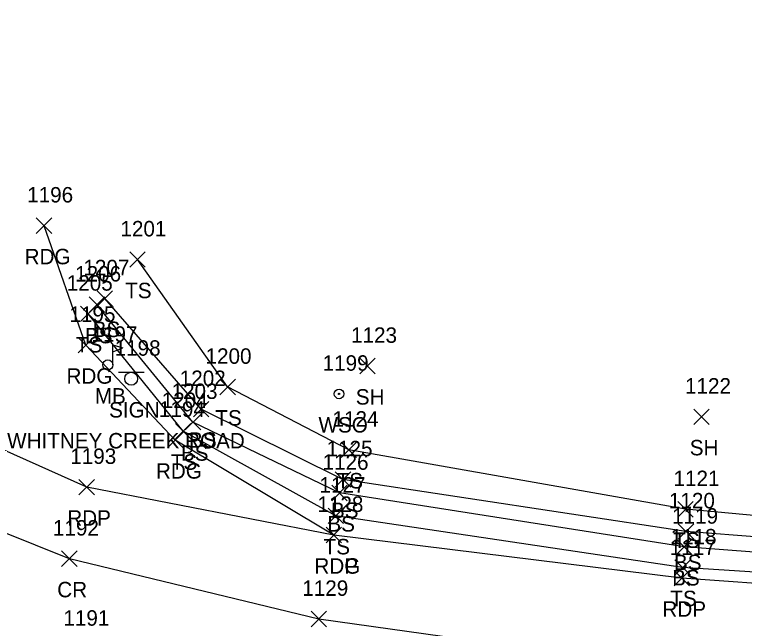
# Model space of a CAD drawing. Extents: x 1401404 to 1403982, y 557481 to 559873.
# Drawn here: x 1403353.7 to 1403448.2, y 558593.7 to 558673.1 of the extents above; entities that cross this region are included whole.
import ezdxf

# ---------------------------------------------------------------- set-up
doc = ezdxf.new("R2010")
doc.units = 0
for name, color, linetype in [('L_A', 7, 'Continuous'), ('L_I', 7, 'Continuous'), ('L_TIC', 7, 'Continuous'), ('LELB', 7, 'Continuous'), ('LMB', 7, 'Continuous'), ('P_A', 7, 'Continuous'), ('P_I', 7, 'Continuous'), ('P_TIC', 7, 'Continuous'), ('PET', 7, 'Continuous'), ('PEU', 7, 'Continuous'), ('PRC', 7, 'Continuous'), ('S_A', 7, 'Continuous'), ('S_C', 7, 'Continuous'), ('S_I', 7, 'Continuous'), ('SSGN', 7, 'Continuous'), ('U_A', 7, 'Continuous'), ('U_I', 7, 'Continuous'), ('UWV', 7, 'Continuous')]:
    doc.layers.add(name, color=color, linetype=linetype)

msp = doc.modelspace()

# ---------------------------------------------------------------- linework, layer by layer
at = {"layer": 'L_TIC'}
for points in [[(1403368.639, 558640.429), (1403370.639, 558642.429)], [(1403370.639, 558640.429), (1403368.639, 558642.429)], [(1403364.413, 558635.397), (1403366.413, 558637.397)], [(1403366.413, 558635.397), (1403364.413, 558637.397)], [(1403363.402, 558634.589), (1403365.402, 558636.589)], [(1403365.402, 558634.589), (1403363.402, 558636.589)], [(1403362.259, 558633.405), (1403364.259, 558635.405)], [(1403364.259, 558633.405), (1403362.259, 558635.405)], [(1403398.403, 558626.651), (1403400.403, 558628.651)], [(1403400.403, 558626.651), (1403398.403, 558628.651)], [(1403380.308, 558623.937), (1403382.308, 558625.937)], [(1403382.308, 558623.937), (1403380.308, 558625.937)], [(1403376.884, 558621.062), (1403378.884, 558623.062)], [(1403378.884, 558621.062), (1403376.884, 558623.062)], [(1403441.621, 558620.082), (1403443.621, 558622.082)], [(1403443.621, 558620.082), (1403441.621, 558622.082)], [(1403375.821, 558619.387), (1403377.821, 558621.387)], [(1403377.821, 558619.387), (1403375.821, 558621.387)], [(1403374.548, 558618.22), (1403376.548, 558620.22)], [(1403376.548, 558618.22), (1403374.548, 558620.22)], [(1403396.004, 558615.801), (1403398.004, 558617.801)], [(1403398.004, 558615.801), (1403396.004, 558617.801)], [(1403395.235, 558611.965), (1403397.235, 558613.965)], [(1403397.235, 558611.965), (1403395.235, 558613.965)], [(1403394.775, 558610.214), (1403396.775, 558612.214)], [(1403396.775, 558610.214), (1403394.775, 558612.214)], [(1403439.565, 558608.101), (1403441.565, 558610.101)], [(1403441.565, 558608.101), (1403439.565, 558610.101)], [(1403394.319, 558607.26), (1403396.319, 558609.26)], [(1403396.319, 558607.26), (1403394.319, 558609.26)], [(1403439.621, 558605.222), (1403441.621, 558607.222)], [(1403441.621, 558605.222), (1403439.621, 558607.222)], [(1403439.389, 558603.238), (1403441.389, 558605.238)], [(1403441.389, 558603.238), (1403439.389, 558605.238)], [(1403439.184, 558600.557), (1403441.184, 558602.557)], [(1403441.184, 558600.557), (1403439.184, 558602.557)]]:
    msp.add_lwpolyline(points, dxfattribs=at)
at = {"layer": 'LELB'}
for points in [[(1403520.57, 558597.512), (1403525.537, 558598.94), (1403526.546, 558602.616), (1403525.251, 558605.144), (1403520.727, 558606.346), (1403491.148, 558604.426), (1403440.565, 558609.101), (1403397.004, 558616.801), (1403381.308, 558624.937), (1403369.639, 558641.429)], [(1403520.408, 558599.041), (1403523.076, 558598.996), (1403523.322, 558600.369), (1403522.192, 558602.407), (1403490.843, 558602.354), (1403440.621, 558606.222), (1403396.235, 558612.965), (1403377.884, 558622.062), (1403365.413, 558636.397)], [(1403520.408, 558599.041), (1403490.768, 558600.416), (1403440.389, 558604.238), (1403395.775, 558611.214), (1403376.821, 558620.387), (1403364.402, 558635.589)], [(1403520.57, 558597.512), (1403490.543, 558598.334), (1403440.184, 558601.557), (1403395.319, 558608.26), (1403375.548, 558619.22), (1403363.259, 558634.405)]]:
    msp.add_lwpolyline(points, dxfattribs=at)
at = {"layer": 'LMB'}
for p, q in [((1403366.465, 558630.387), (1403367.759, 558630.005)), ((1403366.471, 558627.795), (1403366.47, 558630.39)), ((1403366.47, 558629.488), (1403367.752, 558629.996)), ((1403365.815, 558627.787), (1403365.815, 558627.787))]:
    msp.add_line(p, q, dxfattribs=at)
msp.add_circle((1403365.815, 558627.787), 0.656, dxfattribs=at)
at = {"layer": 'P_TIC'}
for points in [[(1403356.547, 558644.818), (1403358.547, 558646.818)], [(1403358.547, 558644.818), (1403356.547, 558646.818)], [(1403361.968, 558629.357), (1403363.968, 558631.357)], [(1403363.968, 558629.357), (1403361.968, 558631.357)], [(1403373.54, 558617.068), (1403375.54, 558619.068)], [(1403375.54, 558617.068), (1403373.54, 558619.068)], [(1403362.07, 558610.974), (1403364.07, 558612.974)], [(1403364.07, 558610.974), (1403362.07, 558612.974)], [(1403394.053, 558604.765), (1403396.053, 558606.765)], [(1403396.053, 558604.765), (1403394.053, 558606.765)], [(1403394.053, 558604.765), (1403396.053, 558606.765)], [(1403396.053, 558604.765), (1403394.053, 558606.765)], [(1403359.826, 558601.705), (1403361.826, 558603.705)], [(1403361.826, 558601.705), (1403359.826, 558603.705)], [(1403439.079, 558599.181), (1403441.079, 558601.181)], [(1403441.079, 558599.181), (1403439.079, 558601.181)], [(1403392.102, 558593.896), (1403394.102, 558595.896)], [(1403394.102, 558593.896), (1403392.102, 558595.896)]]:
    msp.add_lwpolyline(points, dxfattribs=at)
at = {"layer": 'PET'}
msp.add_lwpolyline([(1403552.489, 558594.803), (1403524.494, 558596.024), (1403520.249, 558595.626), (1403487.057, 558596.833), (1403440.079, 558600.181), (1403395.053, 558605.765), (1403363.07, 558611.974), (1403293.663, 558643.036), (1403283.543, 558648.26), (1403256.862, 558665.104), (1403232.936, 558682.451), (1403201.279, 558707.258), (1403164.555, 558736.666), (1403129.248, 558765.781)], dxfattribs=at)
at = {"layer": 'PEU'}
msp.add_lwpolyline([(1403395.053, 558605.765), (1403374.54, 558618.068), (1403362.968, 558630.357), (1403357.547, 558645.818)], dxfattribs=at)
at = {"layer": 'PRC'}
msp.add_lwpolyline([(1403567.874, 558582.773), (1403521.719, 558584.551), (1403486.229, 558585.007), (1403438.972, 558588.433), (1403393.102, 558594.896), (1403360.826, 558602.705), (1403288.915, 558631.603), (1403250.295, 558655.214), (1403225.89, 558672.347), (1403193.368, 558698.042), (1403157.152, 558726.964), (1403121.948, 558757.263), (1403083.224, 558789.984), (1403051.101, 558815.937), (1403004.274, 558851.49), (1402960.213, 558880.82), (1402921.635, 558903.817), (1402881.318, 558926.058), (1402807.323, 558964.726), (1402770.827, 558983.445)], dxfattribs=at)
at = {"layer": 'SSGN'}
for p, q in [((1403367.183, 558626.834), (1403370.516, 558626.834)), ((1403368.83, 558626.001), (1403368.83, 558626.001))]:
    msp.add_line(p, q, dxfattribs=at)
msp.add_circle((1403368.83, 558626.001), 0.833, dxfattribs=at)
at = {"layer": 'UWV'}
for radius in [0.625, 0.0833]:
    msp.add_circle((1403395.734, 558624.038), radius, dxfattribs=at)

# ---------------------------------------------------------------- texts
at = {"layer": 'L_A'}
for s, p in [('TS', (1403368.049, 558636.429)), ('BS', (1403363.854, 558631.397)), ('BS', (1403362.843, 558630.589)), ('TS', (1403361.669, 558629.405)), ('MB', (1403364.122, 558622.787)), ('SH', (1403397.891, 558622.651)), ('TS', (1403379.717, 558619.937)), ('BS', (1403376.325, 558617.062)), ('BS', (1403375.262, 558615.387)), ('SH', (1403441.109, 558616.082)), ('TS', (1403373.957, 558614.22)), ('TS', (1403395.413, 558611.801)), ('BS', (1403394.676, 558607.965)), ('BS', (1403394.215, 558606.214)), ('TS', (1403438.974, 558604.101)), ('TS', (1403393.729, 558603.26)), ('BS', (1403439.062, 558601.222)), ('BS', (1403438.83, 558599.238)), ('TS', (1403438.594, 558596.557))]:
    msp.add_text(s, height=2, dxfattribs=at).set_placement(p)
at = {"layer": 'L_I'}
for s, p in [('1201', (1403367.434, 558644.429)), ('1207', (1403362.641, 558639.397)), ('1206', (1403361.575, 558638.589)), ('1205', (1403360.488, 558637.405)), ('1197', (1403363.689, 558630.787)), ('1123', (1403397.277, 558630.651)), ('1200', (1403378.449, 558627.937)), ('1202', (1403375.112, 558625.062)), ('1122', (1403440.495, 558624.082)), ('1203', (1403374.049, 558623.387)), ('1204', (1403372.776, 558622.22)), ('1124', (1403394.878, 558619.801)), ('1125', (1403394.109, 558615.965)), ('1126', (1403393.593, 558614.214)), ('1121', (1403439.006, 558612.101)), ('1127', (1403393.193, 558611.26)), ('1120', (1403438.409, 558609.222)), ('1119', (1403438.822, 558607.238)), ('1118', (1403438.625, 558604.557))]:
    msp.add_text(s, height=2, dxfattribs=at).set_placement(p)
at = {"layer": 'P_A'}
for s, p in [('RDG', (1403355.035, 558640.818)), ('RDG', (1403360.456, 558625.357)), ('RDG', (1403372.028, 558613.068)), ('RDP', (1403360.558, 558606.974)), ('RDG', (1403392.541, 558600.765)), ('RDP', (1403392.541, 558600.765)), ('CR', (1403359.259, 558597.705)), ('RDP', (1403437.567, 558595.181))]:
    msp.add_text(s, height=2, dxfattribs=at).set_placement(p)
at = {"layer": 'P_I'}
for s, p in [('1196', (1403355.366, 558648.818)), ('1195', (1403360.842, 558633.357)), ('1194', (1403372.414, 558621.068)), ('1193', (1403360.944, 558614.974)), ('1128', (1403392.927, 558608.765)), ('1128', (1403392.927, 558608.765)), ('1192', (1403358.7, 558605.705)), ('1117', (1403438.519, 558603.181)), ('1129', (1403390.969, 558597.896)), ('1191', (1403360.054, 558594.03))]:
    msp.add_text(s, height=2, dxfattribs=at).set_placement(p)
at = {"layer": 'S_A'}
msp.add_text('SIGN', height=2, dxfattribs=at).set_placement((1403365.968, 558620.98))
at = {"layer": 'S_C'}
msp.add_text('WHITNEY CREEK ROAD', height=2, dxfattribs=at).set_placement((1403352.771, 558616.98))
at = {"layer": 'S_I'}
msp.add_text('1198', height=2, dxfattribs=at).set_placement((1403366.684, 558628.98))
at = {"layer": 'U_A'}
msp.add_text('WSO', height=2, dxfattribs=at).set_placement((1403393.064, 558619.038))
at = {"layer": 'U_I'}
msp.add_text('1199', height=2, dxfattribs=at).set_placement((1403393.6, 558627.038))

doc.saveas('drawing.dxf')
